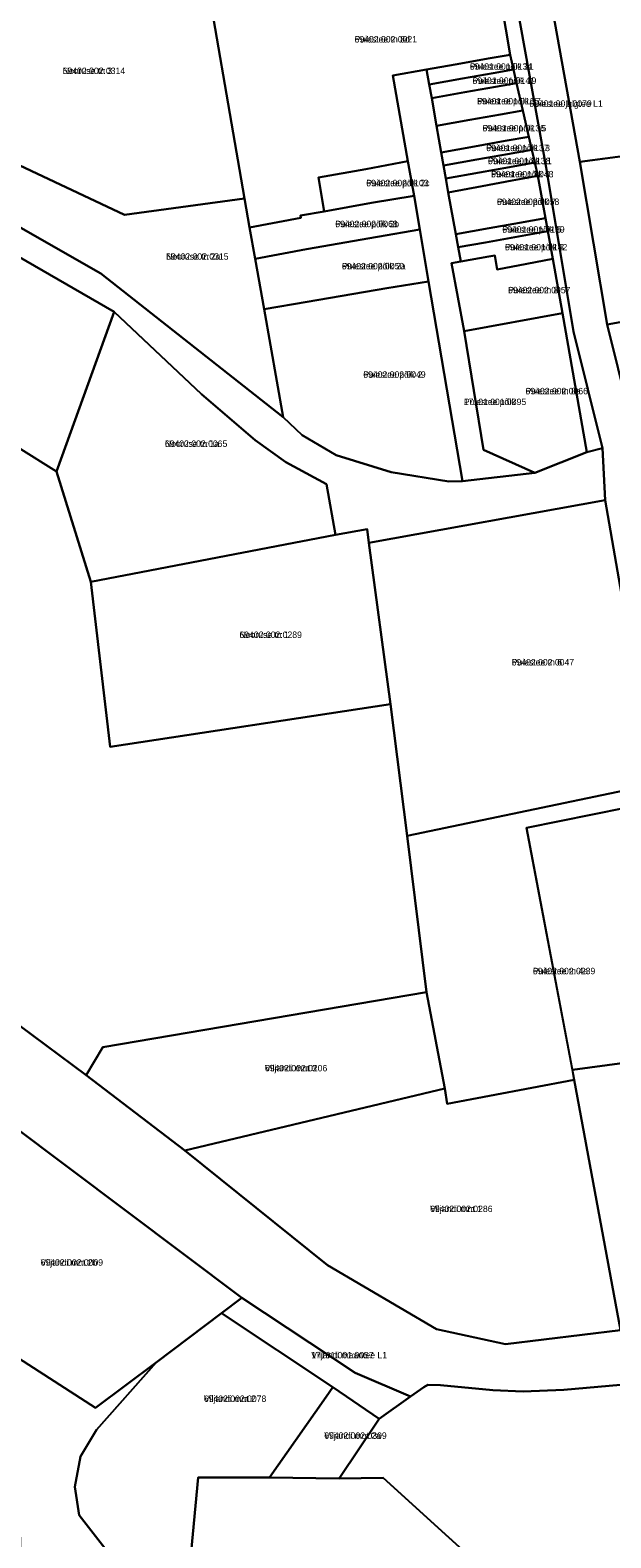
# Model space of a CAD drawing. Extents: x 621116 to 647354, y 6433782 to 6479868.
# Drawn here: x 632180.9 to 632315.8, y 6446793.4 to 6447143.7 of the extents above; entities that cross this region are included whole.
import ezdxf

# ---------------------------------------------------------------- set-up
doc = ezdxf.new("R2010")
doc.units = 0
for name, color, linetype in [('L_AADRESS', 7, 'Continuous'), ('PIIR', 7, 'Continuous'), ('TUNNUS', 7, 'Continuous')]:
    doc.layers.add(name, color=color, linetype=linetype)

msp = doc.modelspace()

# ---------------------------------------------------------------- linework, layer by layer
at = {"layer": 'PIIR'}
for points in [[(632286.2, 6447174.79), (632279.91, 6447212.17), (632284.03, 6447208.63), (632292.47, 6447159.6), (632292.9, 6447155.68), (632300.78, 6447111.8), (632307.16, 6447073.73), (632313.86, 6447046.59), (632310.27, 6447045.67), (632304.59, 6447078.01), (632302.31, 6447090.59), (632301.19, 6447097), (632300.66, 6447100.07), (632298.85, 6447109.91), (632298.19, 6447113.02), (632297.43, 6447115.95), (632296.75, 6447118.96), (632295.36, 6447125.09), (632293.92, 6447131.46), (632293.21, 6447134.58), (632292.47, 6447138.02)], [(632286.2, 6447174.79), (632292.47, 6447138.02), (632287.81, 6447137.2), (632279.62, 6447135.77), (632273, 6447134.6), (632265.17, 6447133.21), (632268.67, 6447113.32), (632258.89, 6447111.46), (632247.89, 6447109.48), (632249.24, 6447101.62), (632243.74, 6447100.64), (632243.77, 6447100.13), (632231.84, 6447097.89), (632230.67, 6447104.66), (632220.09, 6447166.23), (632261.4, 6447171.42)], [(632167.15, 6447159.75), (632220.09, 6447166.23), (632230.67, 6447104.66), (632202.81, 6447100.87), (632147.18, 6447126.98)], [(632355.69, 6447164.73), (632361.61, 6447120.15), (632308.66, 6447113.17), (632300.82, 6447156.82)], [(632273.63, 6447131.1), (632273, 6447134.6), (632279.62, 6447135.77), (632287.81, 6447137.2), (632292.47, 6447138.02), (632293.21, 6447134.58), (632288.47, 6447133.74), (632281.35, 6447132.48)], [(632265.17, 6447133.21), (632273, 6447134.6), (632273.63, 6447131.1), (632274.19, 6447127.95), (632275.33, 6447121.53), (632276.43, 6447115.35), (632276.97, 6447112.31), (632277.51, 6447109.25), (632278.05, 6447106.06), (632279.81, 6447096.32), (632280.35, 6447093.29), (632280.93, 6447090), (632278.83, 6447089.63), (632281.73, 6447073.83), (632286.21, 6447046.25), (632298.14, 6447040.85), (632281.35, 6447038.98), (632273.48, 6447085.37), (632271.44, 6447097.41), (632270.09, 6447105.28), (632268.67, 6447113.32)], [(632274.19, 6447127.95), (632273.63, 6447131.1), (632281.35, 6447132.48), (632288.47, 6447133.74), (632293.21, 6447134.58), (632293.92, 6447131.46), (632289.03, 6447130.59), (632281.91, 6447129.33)], [(632275.33, 6447121.53), (632274.19, 6447127.95), (632281.91, 6447129.33), (632289.03, 6447130.59), (632293.92, 6447131.46), (632295.36, 6447125.09), (632290.17, 6447124.17), (632283.05, 6447122.91)], [(632202.81, 6447100.87), (632230.67, 6447104.66), (632231.84, 6447097.89), (632233.17, 6447090.64), (632235.22, 6447078.91), (632239.71, 6447053.82), (632197.32, 6447087.21), (632148.79, 6447114.89), (632145.29, 6447123.53), (632147.18, 6447126.98)], [(632276.43, 6447115.35), (632275.33, 6447121.53), (632283.05, 6447122.91), (632290.17, 6447124.17), (632295.36, 6447125.09), (632296.75, 6447118.96), (632291.27, 6447117.99), (632284.15, 6447116.72)], [(632276.97, 6447112.31), (632276.43, 6447115.35), (632284.15, 6447116.72), (632291.27, 6447117.99), (632296.75, 6447118.96), (632297.43, 6447115.95), (632291.81, 6447114.95), (632284.69, 6447113.69)], [(632349.47, 6447118.55), (632355.47, 6447082.74), (632315, 6447075.35), (632308.66, 6447113.17)], [(632268.67, 6447113.32), (632270.09, 6447105.28), (632260.24, 6447103.62), (632249.24, 6447101.62), (632247.89, 6447109.48), (632258.89, 6447111.46)], [(632277.51, 6447109.25), (632276.97, 6447112.31), (632284.69, 6447113.69), (632291.81, 6447114.95), (632297.43, 6447115.95), (632298.19, 6447113.02), (632292.31, 6447111.92), (632285.27, 6447110.64)], [(632278.05, 6447106.06), (632277.51, 6447109.25), (632285.27, 6447110.64), (632292.31, 6447111.92), (632298.19, 6447113.02), (632298.85, 6447109.91), (632292.88, 6447108.81), (632285.9, 6447107.48)], [(632142.76, 6447111.5), (632200.39, 6447078.27), (632187.01, 6447041.21), (632124.53, 6447080.23), (632139.33, 6447110.64)], [(632298.85, 6447109.91), (632300.66, 6447100.07), (632294.62, 6447098.96), (632287.54, 6447097.71), (632279.81, 6447096.32), (632278.05, 6447106.06), (632285.9, 6447107.48), (632292.88, 6447108.81)], [(632270.09, 6447105.28), (632271.44, 6447097.41), (632261.63, 6447095.73), (632245.08, 6447092.88), (632233.17, 6447090.64), (632231.84, 6447097.89), (632243.77, 6447100.13), (632243.74, 6447100.64), (632249.24, 6447101.62), (632260.24, 6447103.62)], [(632280.35, 6447093.29), (632279.81, 6447096.32), (632287.54, 6447097.71), (632294.62, 6447098.96), (632300.66, 6447100.07), (632301.19, 6447097), (632295.19, 6447095.93), (632286.71, 6447094.43)], [(632271.44, 6447097.41), (632273.48, 6447085.37), (632263.73, 6447083.82), (632245.25, 6447080.63), (632235.22, 6447078.91), (632233.17, 6447090.64), (632245.08, 6447092.88), (632261.63, 6447095.73)], [(632280.93, 6447090), (632280.35, 6447093.29), (632286.71, 6447094.43), (632295.19, 6447095.93), (632301.19, 6447097), (632302.31, 6447090.59), (632296.33, 6447089.41), (632289.38, 6447088.14), (632288.88, 6447091.38), (632287.45, 6447091.13)], [(632302.31, 6447090.59), (632304.59, 6447078.01), (632281.73, 6447073.83), (632278.83, 6447089.63), (632280.93, 6447090), (632287.45, 6447091.13), (632288.88, 6447091.38), (632289.38, 6447088.14), (632296.33, 6447089.41)], [(632093.6, 6446975.41), (631995.53, 6447049.4), (631993.58, 6447052.43), (631994.22, 6447055.83), (632002.76, 6447087.82), (632054.12, 6447082.79), (632124.53, 6447080.23), (632187.01, 6447041.21), (632194.95, 6447015.56), (632199.45, 6446977.25), (632264.6, 6446987.12), (632268.52, 6446956.57), (632272.99, 6446920.18), (632197.77, 6446907.43), (632193.86, 6446900.9)], [(632273.48, 6447085.37), (632281.35, 6447038.98), (632278.18, 6447038.85), (632264.78, 6447041.07), (632252.02, 6447044.97), (632244.12, 6447049.64), (632239.71, 6447053.82), (632235.22, 6447078.91), (632245.25, 6447080.63), (632263.73, 6447083.82)], [(632315, 6447075.35), (632355.47, 6447082.74), (632394.39, 6447084.73), (632344.64, 6447030.36), (632320.05, 6447055.08)], [(632249.71, 6447038.24), (632251.8, 6447026.49), (632194.95, 6447015.56), (632187.01, 6447041.21), (632200.39, 6447078.27), (632220.69, 6447059.16), (632233.15, 6447048.46), (632240.28, 6447043.35)], [(632304.59, 6447078.01), (632310.27, 6447045.67), (632298.14, 6447040.85), (632286.21, 6447046.25), (632281.73, 6447073.83)], [(632314.49, 6447034.52), (632325.97, 6446968.56), (632268.52, 6446956.57), (632264.6, 6446987.12), (632259.6, 6447024.62)], [(632264.6, 6446987.12), (632199.45, 6446977.25), (632194.95, 6447015.56), (632251.8, 6447026.49), (632259.18, 6447027.77), (632259.6, 6447024.62)], [(632326.89, 6446964.62), (632296.26, 6446958.42), (632307.29, 6446899.81), (632277.79, 6446894.25), (632277.21, 6446897.8), (632272.99, 6446920.18), (632268.52, 6446956.57), (632325.97, 6446968.56)], [(632306.89, 6446902.19), (632296.26, 6446958.42), (632326.89, 6446964.62), (632327.85, 6446964.8), (632336.25, 6446906.14)], [(632216.84, 6446883.42), (632193.86, 6446900.9), (632197.77, 6446907.43), (632272.99, 6446920.18), (632277.21, 6446897.8)], [(632306.89, 6446902.19), (632336.25, 6446906.14), (632345.88, 6446856.63), (632340.12, 6446849.46), (632318.09, 6446841.7), (632307.29, 6446899.81)], [(632318.09, 6446841.7), (632291.35, 6446838.41), (632275.32, 6446841.91), (632250, 6446856.81), (632216.84, 6446883.42), (632277.21, 6446897.8), (632277.79, 6446894.25), (632307.29, 6446899.81)], [(632230.07, 6446849.21), (632225.35, 6446845.6), (632210.18, 6446834.15), (632196.05, 6446823.6), (632178.16, 6446835.13), (632161.11, 6446845.26), (632144.49, 6446854.46), (632146.53, 6446856.73), (632176.14, 6446889.7)], [(632225.35, 6446845.6), (632230.07, 6446849.21), (632256.4, 6446831.72), (632269.25, 6446826.22), (632261.96, 6446821.04), (632251.23, 6446828.41)], [(632251.23, 6446828.41), (632249.63, 6446826.15), (632242.54, 6446816), (632236.49, 6446807.41), (632219.95, 6446807.47), (632216.18, 6446767.93), (632192.28, 6446798.71), (632191.27, 6446805.24), (632192.55, 6446812.31), (632196.3, 6446818.53), (632210.18, 6446834.15), (632225.35, 6446845.6)], [(632210.18, 6446834.15), (632196.3, 6446818.53), (632192.55, 6446812.31), (632191.27, 6446805.24), (632192.28, 6446798.71), (632216.18, 6446767.93), (632215.67, 6446755.07), (632225.32, 6446753.76), (632249.23, 6446699.26), (632268.09, 6446677.86), (632270.2, 6446668.7), (632271.57, 6446644.13), (632258.78, 6446644.31), (632254.45, 6446669.71), (632234.68, 6446690.59), (632226.65, 6446710.09), (632213.18, 6446745.63), (632178.62, 6446789.35), (632178.2, 6446831.81), (632178.16, 6446835.13), (632196.05, 6446823.6)], [(632323.13, 6446752.66), (632262.92, 6446807.33), (632252.65, 6446807.22), (632261.96, 6446821.04), (632269.25, 6446826.22), (632272.4, 6446828.44), (632273.3, 6446828.95), (632276.23, 6446828.92), (632288.42, 6446827.75), (632295.46, 6446827.42), (632304.93, 6446827.8), (632320.73, 6446829.18), (632327.8, 6446829.55), (632331.02, 6446829.25), (632333.06, 6446828.6), (632335.87, 6446827.25), (632337.72, 6446825.15), (632339.46, 6446821.58), (632340.23, 6446818.86), (632340.08, 6446815.51), (632329.9, 6446773.82)], [(632252.65, 6446807.22), (632236.49, 6446807.41), (632242.54, 6446816), (632249.63, 6446826.15), (632251.23, 6446828.41), (632261.96, 6446821.04)], [(632328.11, 6446720.35), (632306.63, 6446717.75), (632300.21, 6446719.1), (632298.61, 6446732.8), (632290.47, 6446731.3), (632291.61, 6446720.7), (632253.64, 6446729.72), (632247.71, 6446750.73), (632225.32, 6446753.76), (632215.67, 6446755.07), (632216.18, 6446767.93), (632219.95, 6446807.47), (632236.49, 6446807.41), (632252.65, 6446807.22), (632262.92, 6446807.33), (632323.13, 6446752.66)]]:
    msp.add_lwpolyline(points, close=True, dxfattribs=at)
for points in [[(632300.82, 6447156.82), (632308.66, 6447113.17), (632315, 6447075.35), (632320.05, 6447055.08), (632324.42, 6447037.08), (632330.74, 6446998.15), (632337.2, 6446961.26), (632354.81, 6446860.66), (632345.88, 6446856.63), (632336.25, 6446906.14), (632327.85, 6446964.8), (632326.89, 6446964.62), (632325.97, 6446968.56), (632314.49, 6447034.52), (632313.86, 6447046.59), (632307.16, 6447073.73), (632300.78, 6447111.8), (632292.9, 6447155.68)], [(632148.79, 6447114.89), (632197.32, 6447087.21), (632239.71, 6447053.82), (632244.12, 6447049.64), (632252.02, 6447044.97), (632264.78, 6447041.07), (632278.18, 6447038.85), (632281.35, 6447038.98), (632298.14, 6447040.85), (632310.27, 6447045.67), (632313.86, 6447046.59), (632314.49, 6447034.52), (632259.6, 6447024.62), (632259.18, 6447027.77), (632251.8, 6447026.49), (632249.71, 6447038.24), (632240.28, 6447043.35), (632233.15, 6447048.46), (632220.69, 6447059.16), (632200.39, 6447078.27), (632142.76, 6447111.5)], [(632129.11, 6446949.02), (632193.86, 6446900.9), (632216.84, 6446883.42), (632250, 6446856.81), (632275.32, 6446841.91), (632291.35, 6446838.41), (632318.09, 6446841.7)], [(632320.73, 6446829.18), (632304.93, 6446827.8), (632295.46, 6446827.42), (632288.42, 6446827.75), (632276.23, 6446828.92), (632273.3, 6446828.95), (632272.4, 6446828.44), (632269.25, 6446826.22), (632256.4, 6446831.72), (632230.07, 6446849.21), (632176.14, 6446889.7)]]:
    msp.add_lwpolyline(points, dxfattribs=at)

# ---------------------------------------------------------------- texts
at = {"layer": 'L_AADRESS'}
for s, p in [('Puiestee tn 8d', (632256.28, 6447140.88)), ('Nooruse tn 3', (632188.44, 6447133.55)), ('Puiestee põik 21', (632283.05, 6447134.56)), ('Puiestee põik 19', (632283.69, 6447131.26)), ('Puiestee põik 17', (632284.75, 6447126.5)), ('Puiestee jalgtee L1', (632296.88, 6447125.93)), ('Puiestee põik 15', (632286.01, 6447120.22)), ('Puiestee põik 13', (632286.85, 6447115.63)), ('Puiestee põik 11', (632287.27, 6447112.6)), ('Puiestee põik 9', (632287.99, 6447109.54)), ('Puiestee põik 2c', (632258.97, 6447107.47)), ('Puiestee põik 7', (632289.34, 6447103.12)), ('Puiestee põik 2b', (632251.78, 6447097.96)), ('Puiestee põik 5', (632290.6, 6447096.68)), ('Puiestee põik 3', (632291.22, 6447092.57)), ('Nooruse tn 2a', (632212.47, 6447090.4)), ('Puiestee põik 2a', (632253.31, 6447088.16)), ('Puiestee tn 8', (632291.94, 6447082.6)), ('Puiestee põik 2', (632258.29, 6447062.97)), ('Puiestee tn 8a', (632296, 6447059.13)), ('Puiestee põik', (632281.66, 6447056.63)), ('Nooruse tn 1a', (632212.19, 6447046.91)), ('Nooruse tn 1', (632229.52, 6447002.51)), ('Puiestee tn 6', (632292.79, 6446996.12)), ('Puiestee tn 4a', (632297.71, 6446924.37)), ('Viljandi mnt 3', (632235.43, 6446901.8)), ('Viljandi mnt 1', (632273.83, 6446869.11)), ('Viljandi mnt 2b', (632183.31, 6446856.65)), ('Viljandi maantee L1', (632246.2, 6446835.12)), ('Viljandi mnt 2', (632221.25, 6446824.99)), ('Viljandi mnt 2a', (632249.23, 6446816.42))]:
    msp.add_text(s, height=1.5, dxfattribs=at).set_placement(p)
at = {"layer": 'TUNNUS'}
for s, p in [('69402:002:0021', (632256.28, 6447140.88)), ('69402:002:0314', (632188.44, 6447133.55)), ('69401:001:0134', (632283.05, 6447134.56)), ('69401:001:0141', (632283.69, 6447131.26)), ('69401:001:0135', (632284.75, 6447126.5)), ('69401:001:0079', (632296.88, 6447125.93)), ('69401:001:0136', (632286.01, 6447120.22)), ('69401:001:0137', (632286.85, 6447115.63)), ('69401:001:0138', (632287.27, 6447112.6)), ('69401:001:0043', (632287.99, 6447109.54)), ('69402:002:0103', (632258.97, 6447107.47)), ('69402:002:0058', (632289.34, 6447103.12)), ('69402:002:0068', (632251.78, 6447097.96)), ('69401:001:0139', (632290.6, 6447096.68)), ('69401:001:0142', (632291.22, 6447092.57)), ('69402:002:0315', (632212.47, 6447090.4)), ('69402:002:0050', (632253.31, 6447088.16)), ('69402:002:0057', (632291.94, 6447082.6)), ('69402:002:0049', (632258.29, 6447062.97)), ('69402:002:0066', (632296, 6447059.13)), ('17101:001:0395', (632281.66, 6447056.63)), ('69402:002:0065', (632212.19, 6447046.91)), ('69402:002:0289', (632229.52, 6447002.51)), ('69402:002:0047', (632292.79, 6446996.12)), ('69402:002:0239', (632297.71, 6446924.37)), ('69402:002:0206', (632235.43, 6446901.8)), ('69402:002:0286', (632273.83, 6446869.11)), ('69402:002:0009', (632183.31, 6446856.65)), ('17101:001:0057', (632246.2, 6446835.12)), ('69402:002:0078', (632221.25, 6446824.99)), ('69402:002:0309', (632249.23, 6446816.42))]:
    msp.add_text(s, height=1.5, dxfattribs=at).set_placement(p)

doc.saveas('drawing.dxf')
